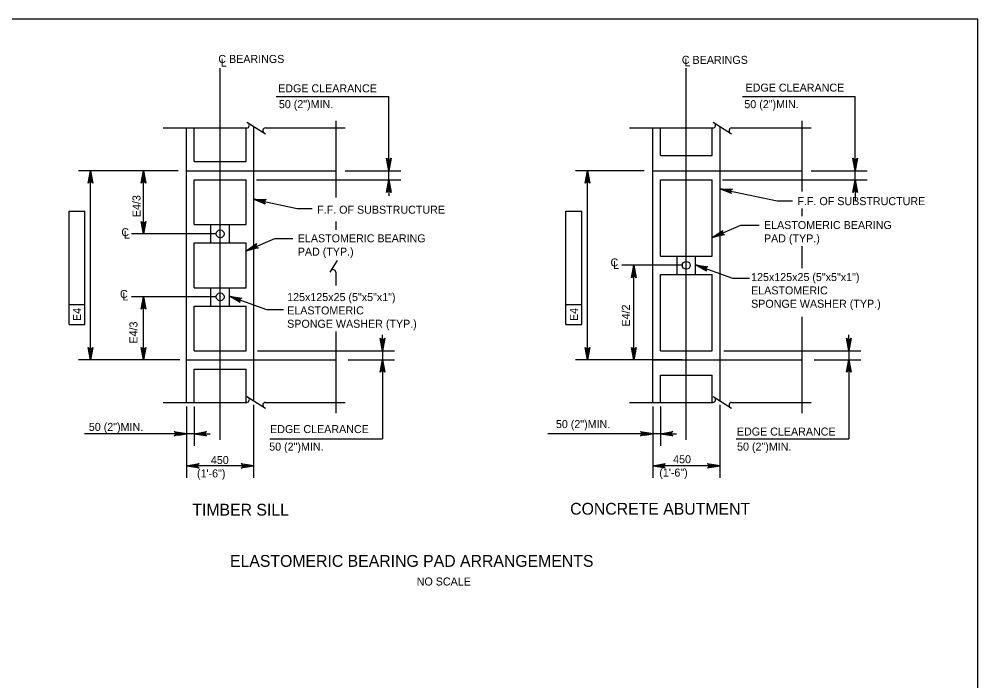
# Model space of a CAD drawing. Extents: x -8 to 75, y -110 to 0.
# Drawn here: x 52.87 to 67.25, y -32.67 to -22.75 of the extents above; entities that cross this region are included whole.
import ezdxf

# ---------------------------------------------------------------- set-up
doc = ezdxf.new("R2010")
doc.units = 0
for name, color, linetype in [('1', 7, 'Continuous'), ('3', 7, 'Continuous'), ('4', 7, 'Continuous'), ('8', 7, 'Continuous')]:
    doc.layers.add(name, color=color, linetype=linetype)

msp = doc.modelspace()

# ---------------------------------------------------------------- linework, layer by layer
at = {"layer": '1'}
msp.add_lwpolyline([(35.75, -43.25), (67.25, -43.25), (67.25, -22.75), (35.75, -22.75)], close=True, dxfattribs=at)
at = {"layer": '3'}
for p, q in [((56.289, -24.293), (56.567, -24.468)), ((57.622, -24.273), (57.622, -25.423)), ((63.28, -24.293), (63.557, -24.468)), ((64.612, -24.273), (64.612, -25.333)), ((55.035, -24.381), (56.286, -24.381)), ((55.386, -28.494), (55.386, -24.381)), ((56.39, -24.357), (56.39, -28.47)), ((56.566, -24.381), (57.762, -24.381)), ((62.026, -24.381), (63.277, -24.381)), ((62.377, -28.494), (62.377, -24.381)), ((63.38, -24.357), (63.38, -28.47)), ((63.557, -24.381), (64.753, -24.381)), ((62.489, -24.793), (63.268, -24.793)), ((55.498, -24.885), (56.277, -24.885)), ((55.029, -25.023), (53.765, -25.023)), ((53.945, -27.857), (53.945, -25.023)), ((55.257, -25.023), (54.423, -25.023)), ((55.386, -25.023), (57.622, -25.023)), ((62.249, -25.023), (61.215, -25.023)), ((61.395, -27.857), (61.395, -25.023)), ((62.377, -25.023), (64.612, -25.023)), ((55.498, -25.16), (56.277, -25.16)), ((62.489, -25.16), (63.268, -25.16)), ((64.612, -25.59), (64.612, -25.703)), ((55.498, -25.83), (56.277, -25.83)), ((55.75, -25.83), (56.026, -25.83)), ((57.622, -25.781), (57.622, -25.908)), ((55.498, -26.105), (56.277, -26.105)), ((64.612, -26.154), (64.612, -26.483)), ((62.489, -26.302), (63.268, -26.302)), ((57.643, -26.369), (57.535, -26.542)), ((57.622, -26.541), (57.622, -26.74)), ((62.489, -26.578), (63.268, -26.578)), ((55.498, -26.775), (56.277, -26.775)), ((55.498, -27.05), (56.277, -27.05)), ((55.75, -27.05), (56.026, -27.05)), ((64.612, -27.212), (64.612, -28.657)), ((57.622, -27.433), (57.622, -28.657)), ((55.498, -27.72), (56.277, -27.72)), ((62.489, -27.72), (63.268, -27.72)), ((55.286, -27.857), (53.765, -27.857)), ((55.386, -27.857), (57.622, -27.857)), ((62.276, -27.857), (61.215, -27.857)), ((62.377, -27.857), (64.612, -27.857)), ((55.498, -27.995), (56.277, -27.995)), ((62.489, -28.087), (63.268, -28.087)), ((56.289, -28.407), (56.567, -28.581)), ((63.28, -28.407), (63.557, -28.581)), ((55.035, -28.494), (56.286, -28.494)), ((56.566, -28.494), (57.762, -28.494)), ((62.026, -28.494), (63.277, -28.494)), ((63.557, -28.494), (64.753, -28.494))]:
    msp.add_line(p, q, dxfattribs=at)
for points in [[(53.925, -25.143), (53.965, -25.143), (53.945, -25.023)], [(61.375, -25.143), (61.415, -25.143), (61.395, -25.023)], [(53.925, -27.737), (53.965, -27.737), (53.945, -27.857)], [(61.375, -27.737), (61.415, -27.737), (61.395, -27.857)]]:
    msp.add_lwpolyline(points, close=True, dxfattribs=at)
for centre, start, end in [((56.286, -24.34), 270, 60), ((56.57, -24.421), 95.3286, 237.8672), ((63.277, -24.34), 270, 60), ((63.56, -24.421), 95.3286, 237.8672), ((57.581, -26.545), 5.3286, 147.8672), ((56.286, -28.453), 270, 60), ((63.277, -28.453), 270, 60), ((56.57, -28.535), 95.3286, 237.8672), ((63.56, -28.535), 95.3286, 237.8672)]:
    msp.add_arc(centre, 0.0409, start, end, dxfattribs=at)
at = {"layer": '4'}
for p, q in [((55.888, -29.058), (55.888, -23.482)), ((62.878, -29.058), (62.878, -23.482)), ((56.729, -23.909), (58.419, -23.909)), ((58.419, -24.903), (58.419, -23.909)), ((63.719, -23.909), (65.41, -23.909)), ((65.41, -25.023), (65.41, -23.909)), ((54.739, -25.968), (54.739, -25.023)), ((57.762, -25.023), (58.599, -25.023)), ((58.419, -25.16), (58.419, -25.023)), ((64.752, -25.023), (65.59, -25.023)), ((65.41, -25.16), (65.41, -25.023)), ((56.432, -25.16), (58.599, -25.16)), ((58.419, -25.28), (58.419, -25.4)), ((63.423, -25.16), (65.59, -25.16)), ((65.41, -25.16), (65.41, -25.475)), ((57.045, -25.587), (57.266, -25.587)), ((64.241, -25.474), (64.473, -25.474)), ((53.624, -27.328), (53.624, -25.627)), ((53.624, -25.627), (53.86, -25.627)), ((53.86, -27.328), (53.86, -25.627)), ((61.074, -27.328), (61.074, -25.627)), ((61.074, -25.627), (61.31, -25.627)), ((61.31, -27.328), (61.31, -25.627)), ((63.697, -25.838), (63.971, -25.838)), ((55.825, -25.968), (54.559, -25.968)), ((56.706, -26.036), (56.98, -26.036)), ((62.816, -26.44), (61.914, -26.44)), ((62.094, -27.857), (62.094, -26.44)), ((63.572, -26.631), (63.827, -26.631)), ((53.624, -27.025), (53.86, -27.025)), ((55.825, -26.912), (54.559, -26.912)), ((54.739, -27.857), (54.739, -26.912)), ((61.074, -27.025), (61.31, -27.025)), ((56.582, -27.103), (56.837, -27.103)), ((53.624, -27.328), (53.86, -27.328)), ((61.074, -27.328), (61.31, -27.328)), ((58.325, -27.6), (58.325, -27.48)), ((65.316, -27.6), (65.316, -27.48)), ((56.45, -27.72), (58.505, -27.72)), ((58.325, -27.72), (58.325, -27.857)), ((63.44, -27.72), (65.495, -27.72)), ((65.316, -27.72), (65.316, -27.857)), ((57.807, -27.857), (58.505, -27.857)), ((62.816, -27.857), (61.914, -27.857)), ((64.798, -27.857), (65.495, -27.857)), ((58.325, -27.977), (58.325, -29.039)), ((65.316, -27.977), (65.316, -29.039)), ((55.386, -28.557), (55.386, -29.144)), ((55.386, -28.557), (55.386, -29.628)), ((55.498, -28.557), (55.498, -29.144)), ((56.39, -28.533), (56.39, -29.628)), ((62.377, -28.557), (62.377, -29.144)), ((62.377, -28.557), (62.377, -29.628)), ((62.489, -28.557), (62.489, -29.144)), ((63.38, -28.533), (63.38, -29.628)), ((55.266, -28.964), (53.855, -28.964)), ((55.498, -28.964), (55.386, -28.964)), ((55.618, -28.964), (55.738, -28.964)), ((56.634, -29.039), (58.325, -29.039)), ((62.256, -28.964), (60.801, -28.964)), ((62.489, -28.964), (62.377, -28.964)), ((62.609, -28.964), (62.729, -28.964)), ((63.625, -29.039), (65.316, -29.039)), ((56.39, -29.448), (55.386, -29.448)), ((63.38, -29.448), (62.377, -29.448))]:
    msp.add_line(p, q, dxfattribs=at)
for points in [[(58.419, -25.023), (58.384, -24.836), (58.394, -24.851), (58.407, -24.858), (58.419, -24.86), (58.432, -24.858), (58.444, -24.851), (58.454, -24.836), (58.419, -25.023), (58.444, -24.851), (58.432, -24.858), (58.419, -25.023), (58.419, -24.86), (58.407, -24.858), (58.419, -25.023), (58.394, -24.851)], [(65.41, -25.023), (65.375, -24.836), (65.385, -24.851), (65.397, -24.858), (65.41, -24.86), (65.422, -24.858), (65.435, -24.851), (65.445, -24.836), (65.41, -25.023), (65.435, -24.851), (65.422, -24.858), (65.41, -25.023), (65.41, -24.86), (65.397, -24.858), (65.41, -25.023), (65.385, -24.851)], [(53.945, -25.023), (53.98, -25.209), (53.97, -25.195), (53.958, -25.187), (53.945, -25.185), (53.933, -25.187), (53.92, -25.195), (53.91, -25.209), (53.945, -25.023), (53.92, -25.195), (53.933, -25.187), (53.945, -25.023), (53.945, -25.185), (53.958, -25.187), (53.945, -25.023), (53.97, -25.195)], [(54.739, -25.023), (54.774, -25.209), (54.764, -25.195), (54.751, -25.187), (54.739, -25.185), (54.726, -25.187), (54.714, -25.195), (54.704, -25.209), (54.739, -25.023), (54.714, -25.195), (54.726, -25.187), (54.739, -25.023), (54.739, -25.185), (54.751, -25.187), (54.739, -25.023), (54.764, -25.195)], [(61.395, -25.023), (61.43, -25.209), (61.42, -25.195), (61.408, -25.187), (61.395, -25.185), (61.383, -25.187), (61.37, -25.195), (61.361, -25.209), (61.395, -25.023), (61.37, -25.195), (61.383, -25.187), (61.395, -25.023), (61.395, -25.185), (61.408, -25.187), (61.395, -25.023), (61.42, -25.195)], [(58.419, -25.16), (58.454, -25.347), (58.444, -25.333), (58.432, -25.325), (58.419, -25.323), (58.407, -25.325), (58.394, -25.333), (58.384, -25.347), (58.419, -25.16), (58.394, -25.333), (58.407, -25.325), (58.419, -25.16), (58.419, -25.323), (58.432, -25.325), (58.419, -25.16), (58.444, -25.333)], [(63.38, -25.293), (64.241, -25.474)], [(63.38, -25.293), (63.57, -25.297), (63.554, -25.304), (63.544, -25.314), (63.539, -25.326), (63.539, -25.339), (63.544, -25.353), (63.556, -25.365), (63.38, -25.293), (63.544, -25.353), (63.539, -25.339), (63.38, -25.293), (63.539, -25.326), (63.544, -25.314), (63.38, -25.293), (63.554, -25.304)], [(65.41, -25.16), (65.445, -25.347), (65.435, -25.333), (65.422, -25.325), (65.41, -25.323), (65.397, -25.325), (65.385, -25.333), (65.375, -25.347), (65.41, -25.16), (65.385, -25.333), (65.397, -25.325), (65.41, -25.16), (65.41, -25.323), (65.422, -25.325), (65.41, -25.16), (65.435, -25.333)], [(56.39, -25.449), (57.045, -25.587)], [(56.39, -25.449), (56.579, -25.454), (56.563, -25.46), (56.553, -25.471), (56.549, -25.483), (56.548, -25.495), (56.553, -25.509), (56.565, -25.522), (56.39, -25.449), (56.553, -25.509), (56.548, -25.495), (56.39, -25.449), (56.549, -25.483), (56.553, -25.471), (56.39, -25.449), (56.563, -25.46)], [(54.739, -25.968), (54.704, -25.781), (54.714, -25.796), (54.726, -25.803), (54.739, -25.805), (54.751, -25.803), (54.764, -25.796), (54.774, -25.781), (54.739, -25.968), (54.764, -25.796), (54.751, -25.803), (54.739, -25.968), (54.739, -25.805), (54.726, -25.803), (54.739, -25.968), (54.714, -25.796)], [(63.268, -26.023), (63.697, -25.838)], [(63.268, -26.023), (63.426, -25.917), (63.416, -25.931), (63.414, -25.946), (63.417, -25.958), (63.424, -25.969), (63.436, -25.977), (63.453, -25.981), (63.268, -26.023), (63.436, -25.977), (63.424, -25.969), (63.268, -26.023), (63.417, -25.958), (63.414, -25.946), (63.268, -26.023), (63.416, -25.931)], [(56.277, -26.221), (56.706, -26.036)], [(56.277, -26.221), (56.435, -26.115), (56.426, -26.13), (56.424, -26.145), (56.427, -26.157), (56.434, -26.168), (56.445, -26.176), (56.462, -26.18), (56.277, -26.221), (56.445, -26.176), (56.434, -26.168), (56.277, -26.221), (56.427, -26.157), (56.424, -26.145), (56.277, -26.221), (56.426, -26.13)], [(62.094, -26.44), (62.129, -26.627), (62.119, -26.612), (62.107, -26.605), (62.094, -26.603), (62.082, -26.605), (62.069, -26.612), (62.059, -26.627), (62.094, -26.44), (62.069, -26.612), (62.082, -26.605), (62.094, -26.44), (62.094, -26.603), (62.107, -26.605), (62.094, -26.44), (62.119, -26.612)], [(63.016, -26.431), (63.572, -26.631)], [(63.016, -26.431), (63.203, -26.461), (63.187, -26.465), (63.175, -26.475), (63.169, -26.486), (63.167, -26.498), (63.17, -26.512), (63.18, -26.527), (63.016, -26.431), (63.17, -26.512), (63.167, -26.498), (63.016, -26.431), (63.169, -26.486), (63.175, -26.475), (63.016, -26.431), (63.187, -26.465)], [(54.739, -26.912), (54.774, -27.099), (54.764, -27.085), (54.751, -27.077), (54.739, -27.075), (54.726, -27.077), (54.714, -27.085), (54.704, -27.099), (54.739, -26.912), (54.714, -27.085), (54.726, -27.077), (54.739, -26.912), (54.739, -27.075), (54.751, -27.077), (54.739, -26.912), (54.764, -27.085)], [(56.026, -26.903), (56.582, -27.103)], [(56.026, -26.903), (56.213, -26.933), (56.196, -26.938), (56.185, -26.947), (56.178, -26.958), (56.176, -26.97), (56.179, -26.985), (56.189, -26.999), (56.026, -26.903), (56.179, -26.985), (56.176, -26.97), (56.026, -26.903), (56.178, -26.958), (56.185, -26.947), (56.026, -26.903), (56.196, -26.938)], [(58.325, -27.72), (58.29, -27.533), (58.3, -27.547), (58.312, -27.555), (58.325, -27.557), (58.337, -27.555), (58.35, -27.547), (58.36, -27.533), (58.325, -27.72), (58.35, -27.547), (58.337, -27.555), (58.325, -27.72), (58.325, -27.557), (58.312, -27.555), (58.325, -27.72), (58.3, -27.547)], [(65.316, -27.72), (65.281, -27.533), (65.29, -27.547), (65.303, -27.555), (65.316, -27.557), (65.328, -27.555), (65.34, -27.547), (65.35, -27.533), (65.316, -27.72), (65.34, -27.547), (65.328, -27.555), (65.316, -27.72), (65.316, -27.557), (65.303, -27.555), (65.316, -27.72), (65.29, -27.547)], [(53.945, -27.857), (53.91, -27.671), (53.92, -27.685), (53.933, -27.693), (53.945, -27.695), (53.958, -27.693), (53.97, -27.685), (53.98, -27.671), (53.945, -27.857), (53.97, -27.685), (53.958, -27.693), (53.945, -27.857), (53.945, -27.695), (53.933, -27.693), (53.945, -27.857), (53.92, -27.685)], [(54.739, -27.857), (54.704, -27.671), (54.714, -27.685), (54.726, -27.693), (54.739, -27.695), (54.751, -27.693), (54.764, -27.685), (54.774, -27.671), (54.739, -27.857), (54.764, -27.685), (54.751, -27.693), (54.739, -27.857), (54.739, -27.695), (54.726, -27.693), (54.739, -27.857), (54.714, -27.685)], [(61.395, -27.857), (61.361, -27.671), (61.37, -27.685), (61.383, -27.693), (61.395, -27.695), (61.408, -27.693), (61.42, -27.685), (61.43, -27.671), (61.395, -27.857), (61.42, -27.685), (61.408, -27.693), (61.395, -27.857), (61.395, -27.695), (61.383, -27.693), (61.395, -27.857), (61.37, -27.685)], [(62.094, -27.857), (62.059, -27.671), (62.069, -27.685), (62.082, -27.693), (62.094, -27.695), (62.107, -27.693), (62.119, -27.685), (62.129, -27.671), (62.094, -27.857), (62.119, -27.685), (62.107, -27.693), (62.094, -27.857), (62.094, -27.695), (62.082, -27.693), (62.094, -27.857), (62.069, -27.685)], [(58.325, -27.855), (58.36, -28.041), (58.35, -28.027), (58.337, -28.019), (58.325, -28.017), (58.312, -28.019), (58.3, -28.027), (58.29, -28.041), (58.325, -27.855), (58.3, -28.027), (58.312, -28.019), (58.325, -27.855), (58.325, -28.017), (58.337, -28.019), (58.325, -27.855), (58.35, -28.027)], [(65.316, -27.857), (65.35, -28.044), (65.34, -28.029), (65.328, -28.022), (65.316, -28.02), (65.303, -28.022), (65.29, -28.029), (65.281, -28.044), (65.316, -27.857), (65.29, -28.029), (65.303, -28.022), (65.316, -27.857), (65.316, -28.02), (65.328, -28.022), (65.316, -27.857), (65.34, -28.029)], [(55.386, -28.964), (55.199, -28.998), (55.214, -28.989), (55.221, -28.976), (55.223, -28.964), (55.221, -28.951), (55.214, -28.939), (55.199, -28.929), (55.386, -28.964), (55.214, -28.939), (55.221, -28.951), (55.386, -28.964), (55.223, -28.964), (55.221, -28.976), (55.386, -28.964), (55.214, -28.989)], [(55.498, -28.964), (55.684, -28.929), (55.67, -28.939), (55.663, -28.951), (55.66, -28.964), (55.663, -28.976), (55.67, -28.989), (55.684, -28.998), (55.498, -28.964), (55.67, -28.989), (55.663, -28.976), (55.498, -28.964), (55.66, -28.964), (55.663, -28.951), (55.498, -28.964), (55.67, -28.939)], [(62.377, -28.964), (62.19, -28.998), (62.204, -28.989), (62.212, -28.976), (62.214, -28.964), (62.212, -28.951), (62.204, -28.939), (62.19, -28.929), (62.377, -28.964), (62.204, -28.939), (62.212, -28.951), (62.377, -28.964), (62.214, -28.964), (62.212, -28.976), (62.377, -28.964), (62.204, -28.989)], [(62.489, -28.964), (62.675, -28.929), (62.661, -28.939), (62.653, -28.951), (62.651, -28.964), (62.653, -28.976), (62.661, -28.989), (62.675, -28.998), (62.489, -28.964), (62.661, -28.989), (62.653, -28.976), (62.489, -28.964), (62.651, -28.964), (62.653, -28.951), (62.489, -28.964), (62.661, -28.939)], [(55.386, -29.448), (55.572, -29.413), (55.558, -29.423), (55.55, -29.436), (55.548, -29.448), (55.55, -29.461), (55.558, -29.473), (55.572, -29.483), (55.386, -29.448), (55.558, -29.473), (55.55, -29.461), (55.386, -29.448), (55.548, -29.448), (55.55, -29.436), (55.386, -29.448), (55.558, -29.423)], [(56.39, -29.448), (56.203, -29.483), (56.218, -29.473), (56.225, -29.461), (56.227, -29.448), (56.225, -29.436), (56.218, -29.423), (56.203, -29.413), (56.39, -29.448), (56.218, -29.423), (56.225, -29.436), (56.39, -29.448), (56.227, -29.448), (56.225, -29.461), (56.39, -29.448), (56.218, -29.473)], [(62.377, -29.448), (62.563, -29.413), (62.549, -29.423), (62.541, -29.436), (62.539, -29.448), (62.541, -29.461), (62.549, -29.473), (62.563, -29.483), (62.377, -29.448), (62.549, -29.473), (62.541, -29.461), (62.377, -29.448), (62.539, -29.448), (62.541, -29.436), (62.377, -29.448), (62.549, -29.423)], [(63.38, -29.448), (63.194, -29.483), (63.208, -29.473), (63.216, -29.461), (63.218, -29.448), (63.216, -29.436), (63.208, -29.423), (63.194, -29.413), (63.38, -29.448), (63.208, -29.423), (63.216, -29.436), (63.38, -29.448), (63.218, -29.448), (63.216, -29.461), (63.38, -29.448), (63.208, -29.473)]]:
    msp.add_lwpolyline(points, dxfattribs=at)
for points in [[(58.399, -24.903), (58.439, -24.903), (58.419, -25.023)], [(65.39, -24.903), (65.43, -24.903), (65.41, -25.023)], [(54.719, -25.143), (54.759, -25.143), (54.739, -25.023)], [(58.399, -25.28), (58.439, -25.28), (58.419, -25.16)], [(63.38, -25.293), (63.496, -25.327), (63.5, -25.308)], [(65.39, -25.28), (65.43, -25.28), (65.41, -25.16)], [(56.39, -25.449), (56.505, -25.484), (56.509, -25.464)], [(54.719, -25.848), (54.759, -25.848), (54.739, -25.968)], [(62.074, -26.56), (62.114, -26.56), (62.094, -26.44)], [(54.719, -27.032), (54.759, -27.032), (54.739, -26.912)], [(58.305, -27.6), (58.345, -27.6), (58.325, -27.72)], [(65.296, -27.6), (65.335, -27.6), (65.316, -27.72)], [(54.719, -27.737), (54.759, -27.737), (54.739, -27.857)], [(58.305, -27.977), (58.345, -27.977), (58.325, -27.857)], [(65.296, -27.977), (65.335, -27.977), (65.316, -27.857)], [(55.266, -28.944), (55.266, -28.984), (55.386, -28.964)], [(55.618, -28.944), (55.618, -28.984), (55.498, -28.964)], [(62.256, -28.944), (62.256, -28.984), (62.377, -28.964)], [(62.609, -28.944), (62.609, -28.984), (62.489, -28.964)], [(55.506, -29.428), (55.506, -29.468), (55.386, -29.448)], [(56.27, -29.428), (56.27, -29.468), (56.39, -29.448)], [(62.496, -29.428), (62.496, -29.468), (62.377, -29.448)], [(63.261, -29.428), (63.261, -29.468), (63.38, -29.448)]]:
    msp.add_lwpolyline(points, close=True, dxfattribs=at)
at = {"layer": '8'}
for p, q in [((55.498, -24.885), (55.498, -24.381)), ((56.277, -24.885), (56.277, -24.381)), ((62.489, -24.793), (62.489, -24.381)), ((63.268, -24.793), (63.268, -24.381)), ((55.498, -25.83), (55.498, -25.16)), ((56.277, -25.83), (56.277, -25.16)), ((62.489, -26.302), (62.489, -25.16)), ((63.268, -26.302), (63.268, -25.16)), ((55.75, -26.105), (55.75, -25.83)), ((56.026, -26.105), (56.026, -25.83)), ((55.498, -26.775), (55.498, -26.105)), ((56.277, -26.775), (56.277, -26.105)), ((62.741, -26.578), (62.741, -26.302)), ((63.016, -26.578), (63.016, -26.302)), ((62.489, -27.72), (62.489, -26.578)), ((63.268, -27.72), (63.268, -26.578)), ((55.75, -27.05), (55.75, -26.775)), ((56.026, -27.05), (56.026, -26.775)), ((55.498, -27.72), (55.498, -27.05)), ((56.277, -27.72), (56.277, -27.05)), ((55.498, -28.494), (55.498, -27.995)), ((56.277, -28.494), (56.277, -27.995)), ((62.489, -28.494), (62.489, -28.087)), ((63.268, -28.494), (63.268, -28.087))]:
    msp.add_line(p, q, dxfattribs=at)
for centre in [(55.888, -25.968), (62.878, -26.44), (55.888, -26.912)]:
    msp.add_circle(centre, 0.059, dxfattribs=at)

# ---------------------------------------------------------------- texts
at = {"layer": '3'}
for s, p in [('TIMBER SILL', (55.471, -30.192)), ('CONCRETE ABUTMENT', (61.137, -30.178)), ('ELASTOMERIC BEARING PAD ARRANGEMENTS', (56.036, -30.96))]:
    msp.add_text(s, height=0.17717, dxfattribs=at).set_placement(p)
at = {"layer": '4'}
for s, p in [('C BEARINGS', (55.861, -23.406)), ('L', (55.898, -23.46)), ('C BEARINGS', (62.811, -23.42)), ('L', (62.849, -23.456)), ('EDGE CLEARANCE', (63.767, -23.836)), ('EDGE CLEARANCE', (56.758, -23.847)), ('50 (2")MIN.', (56.769, -24.084)), ('50 (2")MIN.', (63.749, -24.084)), ('F.F. OF SUBSTRUCTURE', (64.545, -25.538)), ('F.F. OF SUBSTRUCTURE', (57.343, -25.666)), ('ELASTOMERIC BEARING', (64.043, -25.896)), ('C', (54.407, -26.004)), ('L', (54.445, -26.04)), ('ELASTOMERIC BEARING', (57.052, -26.095)), ('PAD (TYP.)', (64.043, -26.096)), ('PAD (TYP.)', (57.052, -26.295)), ('C', (61.742, -26.457)), ('L', (61.78, -26.494)), ('125x125x25 (5"x5"x1")', (63.85, -26.676)), ('C', (54.386, -26.93)), ('L', (54.424, -26.966)), ('125x125x25 (5"x5"x1")', (56.893, -26.976)), ('ELASTOMERIC', (63.85, -26.876)), ('SPONGE WASHER (TYP.)', (63.85, -27.076)), ('ELASTOMERIC', (56.893, -27.176)), ('SPONGE WASHER (TYP.)', (56.893, -27.376)), ('50 (2")MIN.', (53.919, -28.922)), ('EDGE CLEARANCE', (56.637, -28.955)), ('50 (2")MIN.', (60.923, -28.88)), ('EDGE CLEARANCE', (63.637, -28.992)), ('50 (2")MIN.', (56.624, -29.218)), ('50 (2")MIN.', (63.64, -29.218)), ('450', (55.749, -29.419)), ('450', (62.681, -29.407)), ('(1\'-6")', (55.541, -29.619)), ('(1\'-6")', (62.473, -29.607)), ('NO SCALE', (58.836, -31.24))]:
    msp.add_text(s, height=0.12, dxfattribs=at).set_placement(p)
for s, rotation, p in [('E4/3', 90, (54.694, -25.718)), ('E4', 89.9359, (53.802, -27.275)), ('E4', 89.9359, (61.252, -27.275)), ('E4/2', 90, (62.032, -27.358)), ('E4/3', 90, (54.648, -27.613))]:
    msp.add_text(s, height=0.12, rotation=rotation, dxfattribs=at).set_placement(p)

doc.saveas('drawing.dxf')
